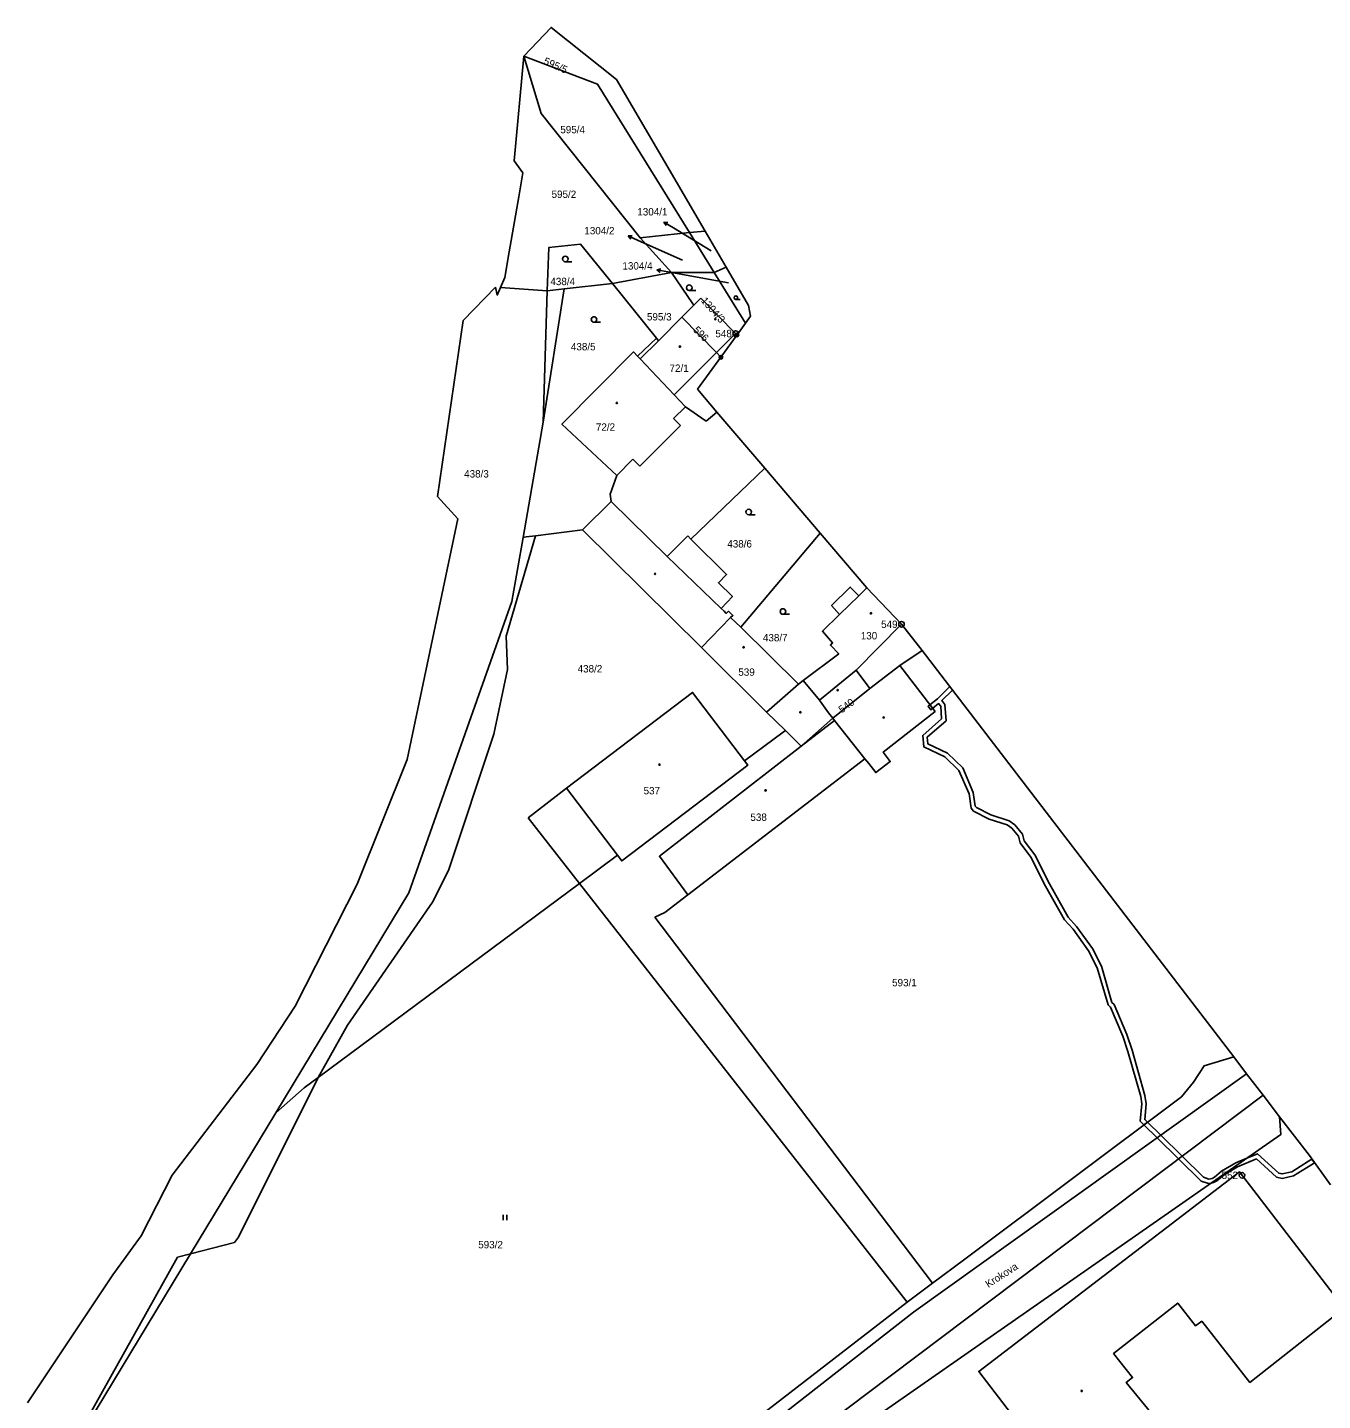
# Model space of a CAD drawing. Extents: x -745926 to -742978, y -968282 to -965689.
# Drawn here: x -745513.5 to -745337.7, y -966109.7 to -965923.3 of the extents above; entities that cross this region are included whole.
import ezdxf

# ---------------------------------------------------------------- set-up
doc = ezdxf.new("R2010")
doc.units = 0
for name, color, linetype in [('Hranice parcel', 7, 'Continuous'), ('Parcelní čísla', 7, 'Continuous'), ('Pop  PČ popisy', 7, 'Continuous'), ('Vnitřní kresba', 7, 'Continuous'), ('Věcná břemena k části', 7, 'Continuous'), ('Značky bodu BP', 7, 'Continuous'), ('Značky budov', 7, 'Continuous'), ('Značky kultur', 7, 'Continuous')]:
    doc.layers.add(name, color=color, linetype=linetype)

msp = doc.modelspace()

# ---------------------------------------------------------------- linework, layer by layer
at = {"layer": 'Hranice parcel'}
for p, q in [((-745430.34, -965951.87), (-745423.64, -965951.15)), ((-745426.11, -965956.54), (-745430.34, -965951.87)), ((-745423.64, -965951.15), (-745421.54, -965950.93)), ((-745423.64, -965951.15), (-745420.31, -965956.54)), ((-745418.67, -965955.84), (-745421.54, -965950.93)), ((-745420.31, -965956.54), (-745418.67, -965955.84)), ((-745415.62, -965961.06), (-745418.67, -965955.84)), ((-745434.12, -965958.06), (-745426.11, -965956.54)), ((-745426.11, -965956.54), (-745420.31, -965956.54)), ((-745416.04, -965963.45), (-745420.31, -965956.54)), ((-745449.98, -965958.55), (-745454.36, -965963.07)), ((-745442.95, -965959.04), (-745449.29, -965958.6)), ((-745443.52, -965976.86), (-745442.95, -965959.04)), ((-745428.14, -965965.48), (-745434.12, -965958.06)), ((-745424.68, -965962.64), (-745423.05, -965961.01)), ((-745423.05, -965961.01), (-745422.09, -965960.06)), ((-745422.09, -965960.06), (-745417.39, -965964.85)), ((-745454.36, -965963.07), (-745457.84, -965986.98)), ((-745420, -965967.44), (-745424.68, -965962.64)), ((-745417.2, -965965.04), (-745419.39, -965968.06)), ((-745417.39, -965964.85), (-745417.2, -965965.04)), ((-745417.2, -965965.04), (-745416.04, -965963.45)), ((-745428.14, -965965.48), (-745430.71, -965967.9)), ((-745422.54, -965972.42), (-745419.39, -965968.06)), ((-745419.39, -965968.06), (-745420, -965967.44)), ((-745419.94, -965975.53), (-745422.54, -965972.42)), ((-745421.37, -965976.72), (-745419.94, -965975.53)), ((-745413.44, -965983.14), (-745419.94, -965975.53)), ((-745446.23, -965992.51), (-745443.52, -965976.86)), ((-745423.46, -965992.74), (-745413.44, -965983.14)), ((-745405.92, -965991.95), (-745413.44, -965983.14)), ((-745457.84, -965986.98), (-745455.1, -965990)), ((-745434.3, -965987.65), (-745438.16, -965991.5)), ((-745455.1, -965990), (-745461.97, -966022.68)), ((-745438.16, -965991.5), (-745422.04, -966007.46)), ((-745416.7, -966004.72), (-745405.92, -965991.95)), ((-745399.59, -965999.37), (-745405.92, -965991.95)), ((-745394.87, -966004.31), (-745399.59, -965999.37)), ((-745422.04, -966007.46), (-745418.07, -966003.4)), ((-745416.7, -966004.72), (-745418.07, -966003.4)), ((-745401.04, -966010.56), (-745394.87, -966004.31)), ((-745392.09, -966007.85), (-745394.87, -966004.31)), ((-745349.78, -966063.04), (-745392.09, -966007.85)), ((-745406.02, -966014.62), (-745401.04, -966010.56)), ((-745399.16, -966013.02), (-745401.04, -966010.56)), ((-745408.23, -966011.95), (-745406.02, -966014.62)), ((-745399.16, -966013.02), (-745404.18, -966017.06)), ((-745438.58, -966039.49), (-745433.43, -966035.66)), ((-745438.58, -966039.49), (-745394.11, -966096.33)), ((-745461.76, -966040.78), (-745479.8, -966070.63)), ((-745339.52, -966076.42), (-745343.56, -966071.16)), ((-745336.64, -966080.42), (-745339.52, -966076.42))]:
    msp.add_line(p, q, dxfattribs=at)
for points in [[(-745421.54, -965950.93), (-745427.05, -965941.49), (-745433.55, -965930.35), (-745442.43, -965923.3), (-745446.12, -965927.2)], [(-745446.12, -965927.2), (-745447.46, -965941.42), (-745446.25, -965943.02), (-745446.81, -965946.28), (-745448.1, -965953.76), (-745448.69, -965957.22), (-745449.29, -965958.6)], [(-745423.64, -965951.15), (-745436.13, -965930.98), (-745446.12, -965927.2)], [(-745430.34, -965951.87), (-745443.8, -965935), (-745446.12, -965927.2)], [(-745434.12, -965958.06), (-745438.42, -965952.73), (-745442.76, -965953.19), (-745442.95, -965959.04)], [(-745423.05, -965961.01), (-745423.2, -965960.82), (-745426.11, -965956.54)], [(-745449.29, -965958.6), (-745449.73, -965959.62), (-745449.98, -965958.55)], [(-745443.52, -965976.86), (-745440.65, -965958.78), (-745434.12, -965958.06)], [(-745416.04, -965963.45), (-745415.38, -965962.51), (-745415.62, -965961.06)], [(-745424.68, -965962.64), (-745427.86, -965965.82), (-745428.14, -965965.48)], [(-745430.71, -965967.9), (-745431.24, -965967.34), (-745440.96, -965977.14), (-745433.53, -965984.11), (-745434.42, -965986.64), (-745434.3, -965987.65)], [(-745430.71, -965967.9), (-745430.34, -965968.29), (-745425.75, -965973.15), (-745424.21, -965974.78), (-745421.37, -965976.72)], [(-745446.23, -965992.51), (-745447.75, -966001.24), (-745461.76, -966040.78)], [(-745438.16, -965991.5), (-745444.55, -965992.3), (-745445.82, -965992.46), (-745446.23, -965992.51)], [(-745418.07, -966003.4), (-745417.76, -966003.13), (-745418.36, -966002.54), (-745418.66, -966002.83), (-745418.95, -966002.55), (-745419.34, -966002.17), (-745417.83, -966000.54), (-745419.73, -965998.67), (-745418.61, -965997.54), (-745423.46, -965992.74)], [(-745399.59, -965999.37), (-745400.67, -966000.43), (-745401.82, -965999.26), (-745404.37, -966001.77), (-745403.3, -966002.97), (-745405.6, -966005.25), (-745404.22, -966006.81), (-745404.52, -966007.15), (-745403.38, -966008.32), (-745408.23, -966011.95)], [(-745408.23, -966011.95), (-745408.86, -966012.46), (-745416.7, -966004.72)], [(-745422.04, -966007.46), (-745413.19, -966016.22), (-745410.64, -966018.74)], [(-745408.49, -966020.87), (-745427.73, -966035.79), (-745423.87, -966041.03), (-745399.85, -966022.56), (-745399.33, -966023.22), (-745398.37, -966024.45), (-745396.39, -966022.95), (-745397.34, -966021.66), (-745390.31, -966016.13), (-745395.11, -966009.92), (-745399.16, -966013.02)], [(-745416.16, -966022.84), (-745423.22, -966013.55), (-745440.34, -966026.57), (-745433.43, -966035.66)], [(-745404.18, -966017.06), (-745404.77, -966016.34), (-745405.69, -966015.06), (-745406.02, -966014.62)], [(-745404.18, -966017.06), (-745403.95, -966017.35), (-745408.49, -966020.87)], [(-745416.16, -966022.84), (-745410.93, -966018.95), (-745410.64, -966018.74)], [(-745410.64, -966018.74), (-745408.54, -966020.82), (-745408.49, -966020.87)], [(-745461.97, -966022.68), (-745468.76, -966039.58), (-745477.16, -966056.16), (-745482.38, -966064.05), (-745493.85, -966079.07), (-745498.05, -966087.31), (-745501.9, -966092.6), (-745513.5, -966109.99)], [(-745433.43, -966035.66), (-745432.84, -966036.43), (-745415.72, -966023.42), (-745416.16, -966022.84)], [(-745479.8, -966070.63), (-745475.94, -966067.23), (-745474.03, -966065.81), (-745438.58, -966039.49)], [(-745394.11, -966096.33), (-745390.66, -966093.76), (-745386.27, -966090.47), (-745356.86, -966068.44), (-745355.23, -966066.46), (-745353.81, -966064.24), (-745349.78, -966063.04)], [(-745343.56, -966071.16), (-745345.8, -966068.23), (-745348.03, -966065.32), (-745349.78, -966063.04)], [(-745506.51, -966114.85), (-745491.36, -966089.76), (-745479.8, -966070.63)], [(-745343.56, -966071.16), (-745343.39, -966073.57), (-745397.2, -966111.09)], [(-745352.67, -966144.81), (-745349.54, -966142.63), (-745347.44, -966141.22), (-745348.55, -966139.72), (-745345.31, -966137.32), (-745349.24, -966132.47), (-745345.73, -966129.95), (-745364.38, -966107.23), (-745363.52, -966106.56), (-745366.08, -966103.31), (-745357.39, -966096.46), (-745354.95, -966099.56), (-745354.13, -966098.91), (-745347.58, -966107.22), (-745334.81, -966097.15), (-745348.98, -966078.65), (-745384.38, -966105.73), (-745379.48, -966112.11), (-745381.34, -966113.54), (-745377.54, -966118.5), (-745375.67, -966117.07), (-745354.77, -966144.32), (-745353.65, -966143.49)], [(-745506.51, -966114.85), (-745495.59, -966121.53), (-745478.55, -966128.66), (-745461.06, -966134.68), (-745455.31, -966136.03), (-745450.03, -966135.78), (-745444.6, -966135.5), (-745440.43, -966132.12), (-745436.33, -966128.95), (-745394.11, -966096.33)]]:
    msp.add_lwpolyline(points, dxfattribs=at)
at = {"layer": 'Pop  PČ popisy'}
for p, q in [((-745425.84, -965950.5), (-745427.13, -965949.73)), ((-745427.13, -965949.73), (-745426.57, -965949.77)), ((-745427.13, -965949.73), (-745426.83, -965950.2)), ((-745431.98, -965951.59), (-745431.42, -965951.56)), ((-745430.61, -965952.2), (-745431.98, -965951.59)), ((-745431.98, -965951.59), (-745431.62, -965952.02)), ((-745424.6, -965954.87), (-745430.61, -965952.2)), ((-745420.7, -965953.63), (-745425.84, -965950.5)), ((-745428.06, -965956.22), (-745427.52, -965956.06)), ((-745426.58, -965956.48), (-745428.06, -965956.22)), ((-745428.06, -965956.22), (-745427.61, -965956.55)), ((-745418.37, -965957.98), (-745426.58, -965956.48))]:
    msp.add_line(p, q, dxfattribs=at)
at = {"layer": 'Vnitřní kresba'}
for p, q in [((-745442.95, -965959.04), (-745440.65, -965958.78)), ((-745417.39, -965964.85), (-745420, -965967.44)), ((-745430.34, -965968.29), (-745427.86, -965965.82)), ((-745425.75, -965973.15), (-745420, -965967.44)), ((-745424.21, -965974.78), (-745425.82, -965976.4)), ((-745425.82, -965976.4), (-745424.88, -965977.34)), ((-745424.88, -965977.34), (-745430.39, -965982.86)), ((-745431.35, -965981.91), (-745433.53, -965984.11)), ((-745430.39, -965982.86), (-745431.35, -965981.91)), ((-745426.68, -965995.13), (-745434.3, -965987.65)), ((-745444.55, -965992.3), (-745448.53, -966005.91)), ((-745423.88, -965992.32), (-745426.68, -965995.13)), ((-745423.46, -965992.74), (-745423.88, -965992.32)), ((-745426.68, -965995.13), (-745419.34, -966002.17)), ((-745403.3, -966002.97), (-745400.67, -966000.43)), ((-745448.53, -966005.91), (-745448.34, -966010.47)), ((-745395.11, -966009.92), (-745392.09, -966007.85)), ((-745448.34, -966010.47), (-745450.21, -966019.21)), ((-745408.86, -966012.46), (-745413.19, -966016.22)), ((-745408.49, -966020.87), (-745404.18, -966017.06)), ((-745403.95, -966017.35), (-745399.85, -966022.56)), ((-745450.21, -966019.21), (-745456.37, -966037.73)), ((-745445.55, -966030.58), (-745440.34, -966026.57)), ((-745438.58, -966039.49), (-745445.55, -966030.58)), ((-745456.37, -966037.73), (-745458.54, -966042.02)), ((-745426.98, -966043.45), (-745423.87, -966041.03)), ((-745458.54, -966042.02), (-745470.08, -966058.75)), ((-745426.98, -966043.45), (-745428.35, -966044.07)), ((-745428.35, -966044.07), (-745390.66, -966093.76)), ((-745470.08, -966058.75), (-745474.03, -966065.81)), ((-745474.03, -966065.81), (-745484.85, -966087.5)), ((-745393.24, -966097.7), (-745348.03, -966065.32)), ((-745345.8, -966068.23), (-745399.54, -966108.73)), ((-745485.4, -966088.25), (-745491.36, -966089.76)), ((-745484.85, -966087.5), (-745485.4, -966088.25)), ((-745491.36, -966089.76), (-745493.12, -966090.21)), ((-745493.12, -966090.21), (-745506.79, -966114.68)), ((-745441.9, -966135.64), (-745393.24, -966097.7)), ((-745399.54, -966108.73), (-745442.8, -966141.18))]:
    msp.add_line(p, q, dxfattribs=at)
at = {"layer": 'Věcná břemena k části'}
for points in [[(-745366.52, -966056.27), (-745364.83, -966060.2), (-745364.15, -966062.31), (-745362.41, -966068.39), (-745362.27, -966069.41), (-745362.47, -966071.78), (-745361.97, -966072.27), (-745361.48, -966071.9), (-745361.85, -966071.54), (-745361.67, -966069.39), (-745361.83, -966068.27), (-745363.57, -966062.13), (-745364.27, -966059.98), (-745366.02, -966055.91), (-745366.32, -966055.64), (-745367.74, -966050.72), (-745368.96, -966048.32), (-745371.12, -966045.33), (-745372.24, -966044.08), (-745374.79, -966039.56), (-745376.78, -966035.62), (-745378.23, -966033.72), (-745378.44, -966032.81), (-745379.5, -966031.55), (-745380.24, -966031.01), (-745382.73, -966030.19), (-745384.7, -966029.18), (-745384.86, -966028.99), (-745385.13, -966027.16), (-745386.57, -966023.8), (-745388.65, -966021.82), (-745391.29, -966020.54), (-745391.38, -966019.63), (-745388.81, -966017.4), (-745388.97, -966015.18), (-745389.4, -966014.68), (-745387.96, -966013.24), (-745388.33, -966012.76), (-745390.01, -966014.44), (-745391.01, -966015.23), (-745391.27, -966015.44), (-745390.9, -966015.91), (-745390.64, -966015.71), (-745389.85, -966015.07), (-745389.55, -966015.42), (-745389.43, -966017.14), (-745392, -966019.39), (-745391.85, -966020.94), (-745388.99, -966022.32), (-745387.07, -966024.14), (-745385.71, -966027.32), (-745385.42, -966029.25), (-745385.08, -966029.66), (-745382.97, -966030.75), (-745380.52, -966031.55), (-745379.92, -966031.99), (-745379, -966033.09), (-745378.79, -966033.98), (-745377.3, -966035.94), (-745375.31, -966039.84), (-745372.74, -966044.44), (-745371.58, -966045.71), (-745369.48, -966048.64), (-745368.3, -966050.94), (-745366.84, -966055.98)], [(-745353.9, -966079.37), (-745356.8, -966076.52), (-745359.69, -966073.67), (-745361.48, -966071.9), (-745361.97, -966072.27), (-745360.18, -966074.02), (-745357.28, -966076.88), (-745354.22, -966079.89), (-745353.21, -966080.23), (-745352.84, -966080.16), (-745348.02, -966076.8), (-745349.51, -966077.42), (-745351.44, -966078.55), (-745352.4, -966079.36), (-745352.73, -966079.52), (-745353.17, -966079.61)], [(-745346.68, -966076.89), (-745343.96, -966079.36), (-745343.22, -966079.54), (-745341.66, -966079.19), (-745339.31, -966077.71), (-745338.82, -966077.4), (-745339.17, -966076.91), (-745339.63, -966077.21), (-745341.9, -966078.63), (-745343.22, -966078.92), (-745343.68, -966078.82), (-745346.56, -966076.19), (-745348.02, -966076.8), (-745352.84, -966080.16), (-745352.53, -966080.1), (-745352.06, -966079.86), (-745351.1, -966079.05), (-745349.25, -966077.96)]]:
    msp.add_lwpolyline(points, close=True, dxfattribs=at)
at = {"layer": 'Značky bodu BP'}
for centre, radius in [((-745417.39, -965964.85), 0.375), ((-745417.2, -965965.04), 0.25), ((-745417.39, -965964.85), 0.015), ((-745417.2, -965965.04), 0.0152), ((-745419.39, -965968.06), 0.25), ((-745419.39, -965968.06), 0.0152), ((-745394.87, -966004.31), 0.375), ((-745394.87, -966004.31), 0.015), ((-745348.66, -966079.11), 0.375), ((-745348.66, -966079.11), 0.015)]:
    msp.add_circle(centre, radius, dxfattribs=at)
at = {"layer": 'Značky budov'}
for centre in [(-745420.14, -965962.89), (-745424.95, -965966.62), (-745433.51, -965974.26), (-745428.31, -965997.47), (-745399.03, -966002.82), (-745416.3, -966007.43), (-745403.53, -966013.25), (-745408.6, -966016.26), (-745397.28, -966016.97), (-745427.72, -966023.36), (-745413.32, -966026.86), (-745370.42, -966108.38)]:
    msp.add_circle(centre, 0.0875, dxfattribs=at)
at = {"layer": 'Značky kultur'}
for p, q in [((-745440.5, -965955.1), (-745439.62, -965955.1)), ((-745423.68, -965959.01), (-745422.8, -965959.01)), ((-745417.35, -965960.23), (-745416.76, -965960.23)), ((-745436.61, -965963.32), (-745435.73, -965963.32)), ((-745415.61, -965989.45), (-745414.73, -965989.45)), ((-745410.97, -966002.96), (-745410.09, -966002.96)), ((-745448.92, -966085.21), (-745448.92, -966084.46)), ((-745448.42, -966085.21), (-745448.42, -966084.46))]:
    msp.add_line(p, q, dxfattribs=at)
for centre, radius in [((-745440.5, -965954.72), 0.375), ((-745423.68, -965958.63), 0.375), ((-745417.35, -965959.98), 0.251), ((-745436.61, -965962.94), 0.375), ((-745415.61, -965989.07), 0.375), ((-745410.97, -966002.58), 0.375)]:
    msp.add_circle(centre, radius, dxfattribs=at)

# ---------------------------------------------------------------- texts
at = {"layer": 'Parcelní čísla'}
for s, rotation, p in [('595/5', 336, (-745443.55, -965928.22)), ('1304/3', 311, (-745422.15, -965960.43)), ('596', 315, (-745423.22, -965964.45)), ('540', 36, (-745402.97, -966016.42))]:
    msp.add_text(s, height=1, rotation=rotation, dxfattribs=at).set_placement(p)
for s, p in [('595/4', (-745441.18, -965937.66)), ('595/2', (-745442.37, -965946.44)), ('1304/1', (-745430.73, -965948.82)), ('1304/2', (-745437.92, -965951.38)), ('1304/4', (-745432.75, -965956.16)), ('438/4', (-745442.53, -965958.28)), ('595/3', (-745429.42, -965963.07)), ('438/5', (-745439.74, -965967.13)), ('72/1', (-745426.36, -965970.05)), ('72/2', (-745436.35, -965978.04)), ('438/3', (-745454.23, -965984.39)), ('438/6', (-745418.52, -965993.89)), ('438/7', (-745413.68, -966006.63)), ('130', (-745400.4, -966006.37)), ('438/2', (-745438.83, -966010.85)), ('539', (-745417.02, -966011.3)), ('537', (-745429.88, -966027.4)), ('538', (-745415.38, -966031)), ('593/1', (-745396.15, -966053.45)), ('593/2', (-745452.32, -966089.02))]:
    msp.add_text(s, height=1, dxfattribs=at).set_placement(p)
at = {"layer": 'Pop  PČ popisy'}
msp.add_text('Krokova', height=1, rotation=33, dxfattribs=at).set_placement((-745383.08, -966094.41))
at = {"layer": 'Značky bodu BP'}
for s, p in [('548', (-745420.13, -965965.35)), ('549', (-745397.64, -966004.81)), ('552', (-745351.43, -966079.61))]:
    msp.add_text(s, height=1, dxfattribs=at).set_placement(p)

doc.saveas('drawing.dxf')
